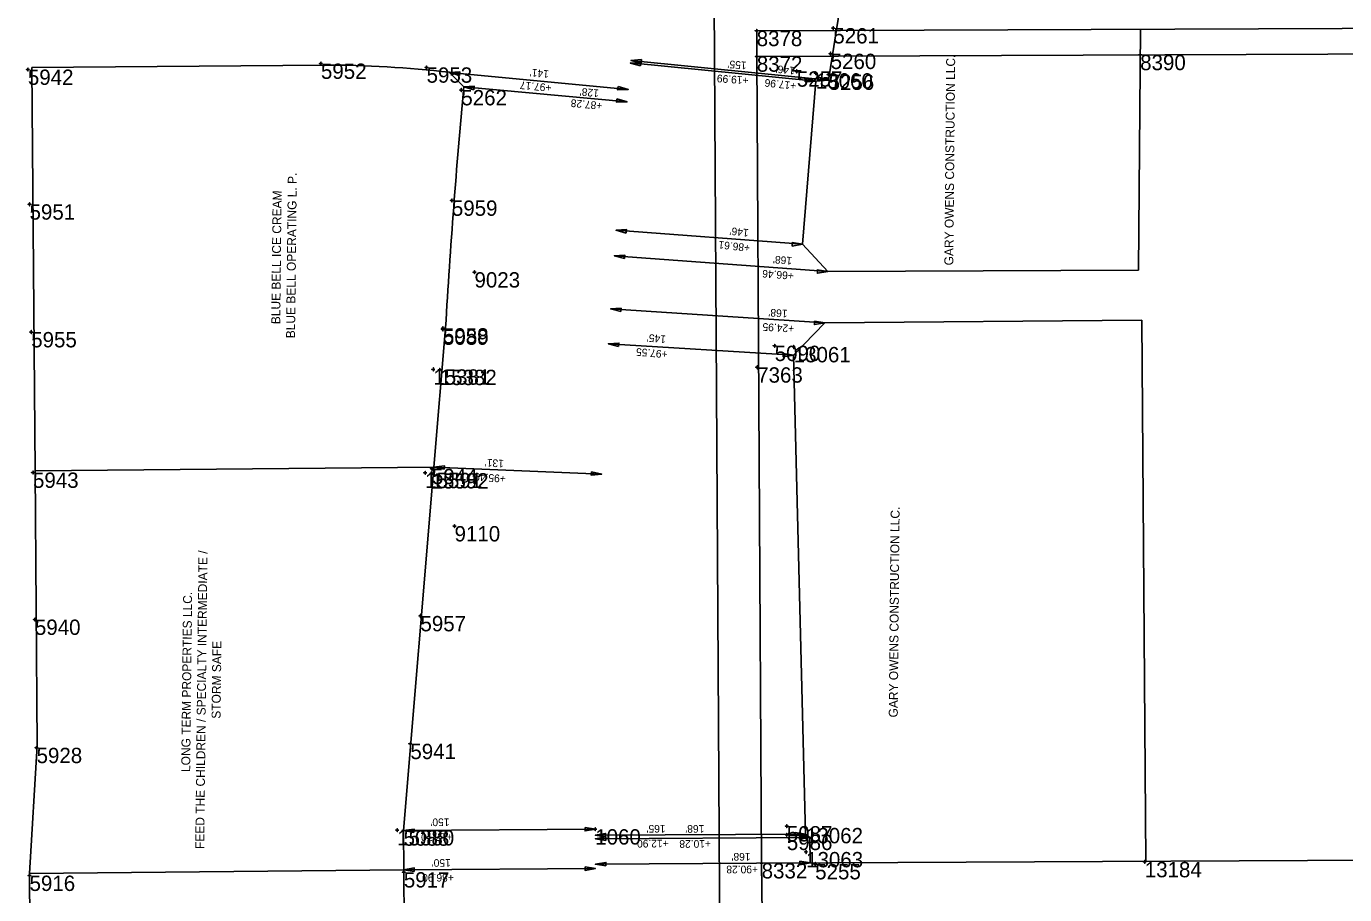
# Model space of a CAD drawing. Extents: x 2145146 to 2158053, y 137507 to 150829.
# Drawn here: x 2150359 to 2151391, y 146286 to 146965 of the extents above; entities that cross this region are included whole.
import ezdxf

# ---------------------------------------------------------------- set-up
doc = ezdxf.new("R2010")
doc.units = 0
for name, color, linetype in [('ALIGN_Cogo Points', 7, 'Continuous'), ('ALIGN_ROW Dimension', 7, 'Continuous'), ('ALIGN_ROW Line', 7, 'Continuous'), ('PLSS_Block Line', 7, 'Continuous'), ('PLSS_Property Line', 7, 'Continuous'), ('PLSS_Section Line', 7, 'Continuous'), ('PLSS_Text_TURNED OFF', 7, 'Continuous')]:
    doc.layers.add(name, color=color, linetype=linetype)

# ---------------------------------------------------------------- blocks, each defined once
blk = doc.blocks.new('Arrowhd')
at = {"layer": 'PLSS_Property Line'}
blk.add_lwpolyline([(0.125, -0.021), (0.125, 0.021), (0, 0)], close=True, dxfattribs=at)

msp = doc.modelspace()

# ---------------------------------------------------------------- linework, layer by layer
at = {"layer": 'ALIGN_Cogo Points'}
for points in [[(2150931, 146961.3), (2150931, 146962.5), (2150931, 146961.3), (2150929.8, 146961.3), (2150931, 146961.3), (2150931, 146960.1), (2150931, 146961.3), (2150932.2, 146961.3)], [(2150991, 146963.4), (2150991, 146964.6), (2150991, 146963.4), (2150989.8, 146963.4), (2150991, 146963.4), (2150991, 146962.2), (2150991, 146963.4), (2150992.2, 146963.4)], [(2150931.1, 146941.3), (2150931.1, 146942.5), (2150931.1, 146941.3), (2150929.9, 146941.3), (2150931.1, 146941.3), (2150931.1, 146940.1), (2150931.1, 146941.3), (2150932.3, 146941.3)], [(2150988.9, 146943.4), (2150988.9, 146944.6), (2150988.9, 146943.4), (2150987.7, 146943.4), (2150988.9, 146943.4), (2150988.9, 146942.2), (2150988.9, 146943.4), (2150990.1, 146943.4)], [(2151231.2, 146942.5), (2151231.2, 146943.7), (2151231.2, 146942.5), (2151230, 146942.5), (2151231.2, 146942.5), (2151231.2, 146941.3), (2151231.2, 146942.5), (2151232.4, 146942.5)], [(2150360.5, 146931), (2150360.5, 146932.2), (2150360.5, 146931), (2150359.3, 146931), (2150360.5, 146931), (2150360.5, 146929.8), (2150360.5, 146931), (2150361.7, 146931)], [(2150589.9, 146935.7), (2150589.9, 146936.9), (2150589.9, 146935.7), (2150588.7, 146935.7), (2150589.9, 146935.7), (2150589.9, 146934.5), (2150589.9, 146935.7), (2150591.1, 146935.7)], [(2150672.6, 146932.7), (2150672.6, 146933.9), (2150672.6, 146932.7), (2150671.4, 146932.7), (2150672.6, 146932.7), (2150672.6, 146931.5), (2150672.6, 146932.7), (2150673.8, 146932.7)], [(2150962.4, 146929.6), (2150962.4, 146930.8), (2150962.4, 146929.6), (2150961.2, 146929.6), (2150962.4, 146929.6), (2150962.4, 146928.4), (2150962.4, 146929.6), (2150963.6, 146929.6)], [(2150977.3, 146928.1), (2150977.3, 146929.3), (2150977.3, 146928.1), (2150976.1, 146928.1), (2150977.3, 146928.1), (2150977.3, 146926.9), (2150977.3, 146928.1), (2150978.5, 146928.1)], [(2150987.3, 146927.1), (2150987.3, 146928.3), (2150987.3, 146927.1), (2150986.1, 146927.1), (2150987.3, 146927.1), (2150987.3, 146925.9), (2150987.3, 146927.1), (2150988.5, 146927.1)], [(2150699.8, 146915), (2150699.8, 146916.2), (2150699.8, 146915), (2150698.6, 146915), (2150699.8, 146915), (2150699.8, 146913.8), (2150699.8, 146915), (2150701, 146915)], [(2150361.8, 146825.6), (2150361.8, 146826.8), (2150361.8, 146825.6), (2150360.6, 146825.6), (2150361.8, 146825.6), (2150361.8, 146824.4), (2150361.8, 146825.6), (2150363, 146825.6)], [(2150692.4, 146828.6), (2150692.4, 146829.8), (2150692.4, 146828.6), (2150691.2, 146828.6), (2150692.4, 146828.6), (2150692.4, 146827.4), (2150692.4, 146828.6), (2150693.6, 146828.6)], [(2150710.1, 146772.5), (2150710.1, 146773.7), (2150710.1, 146772.5), (2150708.9, 146772.5), (2150710.1, 146772.5), (2150710.1, 146771.3), (2150710.1, 146772.5), (2150711.3, 146772.5)], [(2150363.1, 146725.7), (2150363.1, 146726.9), (2150363.1, 146725.7), (2150361.9, 146725.7), (2150363.1, 146725.7), (2150363.1, 146724.5), (2150363.1, 146725.7), (2150364.3, 146725.7)], [(2150685.4, 146728.7), (2150685.4, 146729.9), (2150685.4, 146728.7), (2150684.2, 146728.7), (2150685.4, 146728.7), (2150685.4, 146727.5), (2150685.4, 146728.7), (2150686.6, 146728.7)], [(2150685.4, 146727.7), (2150685.4, 146728.9), (2150685.4, 146727.7), (2150684.2, 146727.7), (2150685.4, 146727.7), (2150685.4, 146726.5), (2150685.4, 146727.7), (2150686.6, 146727.7)], [(2150945.1, 146715), (2150945.1, 146716.2), (2150945.1, 146715), (2150943.9, 146715), (2150945.1, 146715), (2150945.1, 146713.8), (2150945.1, 146715), (2150946.3, 146715)], [(2150960, 146714), (2150960, 146715.2), (2150960, 146714), (2150958.8, 146714), (2150960, 146714), (2150960, 146712.8), (2150960, 146714), (2150961.2, 146714)], [(2150677.9, 146696.5), (2150677.9, 146697.7), (2150677.9, 146696.5), (2150676.7, 146696.5), (2150677.9, 146696.5), (2150677.9, 146695.3), (2150677.9, 146696.5), (2150679.1, 146696.5)], [(2150682.9, 146696.2), (2150682.9, 146697.4), (2150682.9, 146696.2), (2150681.7, 146696.2), (2150682.9, 146696.2), (2150682.9, 146695), (2150682.9, 146696.2), (2150684.1, 146696.2)], [(2150931.4, 146698.1), (2150931.4, 146699.3), (2150931.4, 146698.1), (2150930.2, 146698.1), (2150931.4, 146698.1), (2150931.4, 146696.9), (2150931.4, 146698.1), (2150932.6, 146698.1)], [(2150676.8, 146618.7), (2150676.8, 146619.9), (2150676.8, 146618.7), (2150675.6, 146618.7), (2150676.8, 146618.7), (2150676.8, 146617.5), (2150676.8, 146618.7), (2150678, 146618.7)], [(2150364.5, 146615.8), (2150364.5, 146617), (2150364.5, 146615.8), (2150363.3, 146615.8), (2150364.5, 146615.8), (2150364.5, 146614.6), (2150364.5, 146615.8), (2150365.7, 146615.8)], [(2150671.5, 146615.6), (2150671.5, 146616.8), (2150671.5, 146615.6), (2150670.3, 146615.6), (2150671.5, 146615.6), (2150671.5, 146614.4), (2150671.5, 146615.6), (2150672.7, 146615.6)], [(2150676.5, 146615.3), (2150676.5, 146616.5), (2150676.5, 146615.3), (2150675.3, 146615.3), (2150676.5, 146615.3), (2150676.5, 146614.1), (2150676.5, 146615.3), (2150677.7, 146615.3)], [(2150694.5, 146573.9), (2150694.5, 146575.1), (2150694.5, 146573.9), (2150693.3, 146573.9), (2150694.5, 146573.9), (2150694.5, 146572.7), (2150694.5, 146573.9), (2150695.7, 146573.9)], [(2150366, 146500.8), (2150366, 146502), (2150366, 146500.8), (2150364.8, 146500.8), (2150366, 146500.8), (2150366, 146499.6), (2150366, 146500.8), (2150367.2, 146500.8)], [(2150667.8, 146503.6), (2150667.8, 146504.8), (2150667.8, 146503.6), (2150666.6, 146503.6), (2150667.8, 146503.6), (2150667.8, 146502.4), (2150667.8, 146503.6), (2150669, 146503.6)], [(2150659.9, 146403.6), (2150659.9, 146404.8), (2150659.9, 146403.6), (2150658.7, 146403.6), (2150659.9, 146403.6), (2150659.9, 146402.4), (2150659.9, 146403.6), (2150661.1, 146403.6)], [(2150367.3, 146400.5), (2150367.3, 146401.7), (2150367.3, 146400.5), (2150366.1, 146400.5), (2150367.3, 146400.5), (2150367.3, 146399.3), (2150367.3, 146400.5), (2150368.5, 146400.5)], [(2150649.6, 146336.1), (2150649.6, 146337.3), (2150649.6, 146336.1), (2150648.4, 146336.1), (2150649.6, 146336.1), (2150649.6, 146334.9), (2150649.6, 146336.1), (2150650.8, 146336.1)], [(2150654.6, 146335.9), (2150654.6, 146337.1), (2150654.6, 146335.9), (2150653.4, 146335.9), (2150654.6, 146335.9), (2150654.6, 146334.7), (2150654.6, 146335.9), (2150655.8, 146335.9)], [(2150804.6, 146336.8), (2150804.6, 146338), (2150804.6, 146336.8), (2150803.4, 146336.8), (2150804.6, 146336.8), (2150804.6, 146335.6), (2150804.6, 146336.8), (2150805.8, 146336.8)], [(2150954.6, 146339.2), (2150954.6, 146340.4), (2150954.6, 146339.2), (2150953.4, 146339.2), (2150954.6, 146339.2), (2150954.6, 146338), (2150954.6, 146339.2), (2150955.8, 146339.2)], [(2150954.6, 146332.5), (2150954.6, 146333.7), (2150954.6, 146332.5), (2150953.4, 146332.5), (2150954.6, 146332.5), (2150954.6, 146331.3), (2150954.6, 146332.5), (2150955.8, 146332.5)], [(2150969.6, 146337.8), (2150969.6, 146339), (2150969.6, 146337.8), (2150968.4, 146337.8), (2150969.6, 146337.8), (2150969.6, 146336.6), (2150969.6, 146337.8), (2150970.8, 146337.8)], [(2150969.7, 146319), (2150969.7, 146320.2), (2150969.7, 146319), (2150968.5, 146319), (2150969.7, 146319), (2150969.7, 146317.8), (2150969.7, 146319), (2150970.9, 146319)], [(2150934.9, 146310.3), (2150934.9, 146311.5), (2150934.9, 146310.3), (2150933.7, 146310.3), (2150934.9, 146310.3), (2150934.9, 146309.1), (2150934.9, 146310.3), (2150936.1, 146310.3)], [(2150976.8, 146309.6), (2150976.8, 146310.8), (2150976.8, 146309.6), (2150975.6, 146309.6), (2150976.8, 146309.6), (2150976.8, 146308.4), (2150976.8, 146309.6), (2150978, 146309.6)], [(2151234.8, 146311.2), (2151234.8, 146312.4), (2151234.8, 146311.2), (2151233.6, 146311.2), (2151234.8, 146311.2), (2151234.8, 146310), (2151234.8, 146311.2), (2151236, 146311.2)], [(2150361.8, 146300.5), (2150361.8, 146301.7), (2150361.8, 146300.5), (2150360.6, 146300.5), (2150361.8, 146300.5), (2150361.8, 146299.3), (2150361.8, 146300.5), (2150363, 146300.5)], [(2150654.8, 146303.2), (2150654.8, 146304.4), (2150654.8, 146303.2), (2150653.6, 146303.2), (2150654.8, 146303.2), (2150654.8, 146302), (2150654.8, 146303.2), (2150656, 146303.2)]]:
    msp.add_lwpolyline(points, dxfattribs=at)
at = {"layer": 'ALIGN_ROW Dimension'}
for p, q in [((2150830.4, 146915.5), (2150690.5, 146928.8)), ((2150977.2, 146921.8), (2150832.4, 146936.2)), ((2150987.2, 146922.8), (2150832.6, 146938.2)), ((2150829.5, 146905.7), (2150701.7, 146917.6)), ((2150966.9, 146794.3), (2150821, 146805.3)), ((2150986.6, 146773.1), (2150819.5, 146785.3)), ((2150984.3, 146732.9), (2150816.6, 146743.8)), ((2150959.9, 146707.7), (2150814.9, 146716.5)), ((2150809.7, 146614.6), (2150678.4, 146620.1)), ((2150804.6, 146336.8), (2150654.6, 146335.9)), ((2150969.2, 146333), (2150804.6, 146332.1)), ((2150972.7, 146330.4), (2150804.7, 146329.4)), ((2150972.8, 146310.4), (2150804.8, 146309.4)), ((2150804.8, 146306), (2150654.8, 146305.1))]:
    msp.add_line(p, q, dxfattribs=at)
at = {"layer": 'ALIGN_ROW Line'}
for p, q in [((2150987.2, 146922.8), (2150996.4, 146980.2)), ((2150363.7, 146932.7), (2150592.8, 146934.5)), ((2150690.5, 146928.8), (2150701.7, 146917.6)), ((2150977.2, 146921.8), (2150966.9, 146794.3)), ((2150987.2, 146922.8), (2150977.2, 146921.8)), ((2150986.6, 146773.1), (2150966.9, 146794.3)), ((2150959.9, 146707.7), (2150984.3, 146732.9)), ((2150984.3, 146732.9), (2151232.4, 146734.9)), ((2150678.4, 146620.1), (2150687.5, 146729.1)), ((2150959.9, 146707.7), (2150969.2, 146333)), ((2150654.6, 146335.9), (2150678.4, 146620.1)), ((2150654.8, 146305.1), (2150654.6, 146335.9)), ((2150969.2, 146333), (2150972.7, 146330.4)), ((2150972.7, 146330.4), (2150972.8, 146310.4)), ((2150656.9, 145954.2), (2150654.8, 146305.1))]:
    msp.add_line(p, q, dxfattribs=at)
msp.add_lwpolyline([(2151230, 146774.1), (2150986.6, 146773.1)], dxfattribs=at)
for centre, radius, start, end in [((2150592.8, 146083), 851.5, 83.4143, 90), ((2156534.4, 146382.6), 5857.2, 174.75892, 176.60802)]:
    msp.add_arc(centre, radius, start, end, dxfattribs=at)
at = {"layer": 'PLSS_Block Line'}
for p, q in [((2150366.1, 146617.2), (2150363.7, 146932.7)), ((2150367.8, 146402.2), (2150366.1, 146617.2)), ((2150361.8, 146302.2), (2150367.8, 146402.2)), ((2150363.9, 145951.2), (2150361.8, 146302.2))]:
    msp.add_line(p, q, dxfattribs=at)
for points in [[(2150931, 146961.3), (2153549.3, 146971.8)], [(2150938.9, 145639.2), (2150935.2, 146270.3), (2150934.9, 146310.3), (2150931.1, 146941.3), (2150931, 146961.3)], [(2153549.4, 146951.8), (2150931.1, 146941.3)], [(2150934.9, 146310.3), (2153552, 146323)]]:
    msp.add_lwpolyline(points, dxfattribs=at)
at = {"layer": 'PLSS_Property Line'}
for p, q in [((2151232.4, 146734.9), (2151235.5, 146311.7)), ((2150366.1, 146617.2), (2150678.4, 146620.1)), ((2150654.8, 146305.1), (2150361.8, 146302.2))]:
    msp.add_line(p, q, dxfattribs=at)
msp.add_lwpolyline([(2151231.4, 146962.5), (2151230, 146774.1)], dxfattribs=at)
at = {"layer": 'PLSS_Section Line'}
msp.add_lwpolyline([(2150905.8, 145639), (2150890, 148284.8)], dxfattribs=at)

# ---------------------------------------------------------------- block references
at = {"layer": 'ALIGN_ROW Dimension'}
for p, xscale, yscale, rotation in [((2150832.6, 146938.2), 65, 65.00000000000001, -5.741718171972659), ((2150690.5, 146928.8), 65, 64.99999999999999, -7.374005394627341), ((2150832.2, 146936), 65, 65.00000000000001, -5.741718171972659), ((2150701.7, 146917.6), 65, 64.99999999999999, -7.374005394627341), ((2150977.2, 146921.8), 65, 65, 173.10657989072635), ((2150987.2, 146922.8), 64.99999999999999, 65, 174.47926723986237), ((2150830.4, 146915.5), 65, 64.99999999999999, 173.01404764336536), ((2150829.5, 146905.7), 65, 64.99999999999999, 172.79881966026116), ((2150821, 146805.3), 65, 65.00000000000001, -5.741718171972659), ((2150966.9, 146794.3), 65.00000000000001, 64.99999999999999, -179.65177652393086), ((2150819.5, 146785.3), 65, 65.00000000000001, -5.741718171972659), ((2150986.6, 146773.1), 65.00000000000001, 64.99999999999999, -179.65177652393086), ((2150816.6, 146743.8), 65, 65.00000000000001, -5.741718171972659), ((2150984.3, 146732.9), 65.00000000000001, 64.99999999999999, -179.65177652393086), ((2150814.9, 146716.5), 65, 65.00000000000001, -5.741718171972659), ((2150959.9, 146707.7), 65.00000000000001, 64.99999999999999, -179.65177652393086), ((2150678.4, 146620.1), 65, 65, -2.676263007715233), ((2150809.7, 146614.6), 65, 64.99999999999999, 176.73452931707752), ((2150654.6, 146335.9), 65, 65, -2.676263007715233), ((2150804.8, 146336.9), 65.00000000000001, 64.99999999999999, -179.65177652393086), ((2150804.6, 146332.1), 65, 65, 0.2668843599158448), ((2150804.7, 146329.4), 65, 65, 0.2668843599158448), ((2150969.2, 146333), 65.00000000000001, 64.99999999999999, -179.65177652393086), ((2150972.7, 146330.4), 65.00000000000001, 64.99999999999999, -179.65177652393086), ((2150804.8, 146309.4), 65, 65, 0.2668843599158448), ((2150972.8, 146310.4), 65.00000000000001, 64.99999999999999, -179.65177652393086), ((2150654.8, 146305.1), 65, 65, 0.2668843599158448), ((2150804.8, 146306), 65.00000000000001, 64.99999999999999, -179.65177652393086)]:
    msp.add_blockref('Arrowhd', p, dxfattribs=dict(at, xscale=xscale, yscale=yscale, rotation=rotation))

# ---------------------------------------------------------------- texts
at = {"layer": 'ALIGN_Cogo Points'}
for s, p in [('8378', (2150931, 146949.3)), ('5261', (2150991, 146951.4)), ('8372', (2150931.1, 146929.3)), ('5260', (2150988.9, 146931.4)), ('8390', (2151231.2, 146930.5)), ('5942', (2150360.5, 146919)), ('5952', (2150589.9, 146923.7)), ('5953', (2150672.6, 146920.7)), ('5257', (2150962.4, 146917.6)), ('13060', (2150977.3, 146916.1)), ('5256', (2150987.3, 146915.1)), ('5262', (2150699.8, 146903)), ('5951', (2150361.8, 146813.6)), ('5959', (2150692.4, 146816.6)), ('9023', (2150710.1, 146760.5)), ('5955', (2150363.1, 146713.7)), ('5089', (2150685.4, 146715.7)), ('5958', (2150685.4, 146716.7)), ('5090', (2150945.1, 146703)), ('13061', (2150960, 146702)), ('15381', (2150677.9, 146684.5)), ('15382', (2150682.9, 146684.2)), ('7363', (2150931.4, 146686.1)), ('5943', (2150364.5, 146603.8)), ('15591', (2150671.5, 146603.6)), ('5944', (2150676.8, 146606.7)), ('15592', (2150676.5, 146603.3)), ('9110', (2150694.5, 146561.9)), ('5940', (2150366, 146488.8)), ('5957', (2150667.8, 146491.6)), ('5941', (2150659.9, 146391.6)), ('5928', (2150367.3, 146388.5)), ('15380', (2150649.6, 146324.1)), ('5088', (2150654.6, 146323.9)), ('1060', (2150804.6, 146324.8)), ('5087', (2150954.6, 146327.2)), ('5986', (2150954.6, 146320.5)), ('13062', (2150969.6, 146325.8)), ('8332', (2150934.9, 146298.3)), ('13063', (2150969.7, 146307)), ('5255', (2150976.8, 146297.6)), ('13184', (2151234.8, 146299.2)), ('5916', (2150361.8, 146288.5)), ('5917', (2150654.8, 146291.2))]:
    msp.add_text(s, height=12, dxfattribs=at).set_placement(p)
at = {"layer": 'ALIGN_ROW Dimension'}
for s, rotation, p in [("141'", 174.6652, (2150768.6, 146930.3)), ("155'", 175.7952, (2150923.3, 146937.1)), ("146'", 174.0109, (2150961.1, 146932.9)), ('+97.17', 174.6652, (2150770.6, 146919.5)), ('+19.99', 175.7952, (2150924.8, 146925.3)), ('+17.96', 174.0109, (2150962.2, 146921.1)), ("128'", 174.6652, (2150807.7, 146915.3)), ('+87.28', 174.6652, (2150810.4, 146905.5)), ("146'", 173.7185, (2150925, 146806.1)), ('+86.61', 173.7185, (2150926.1, 146794.3)), ("168'", 175.5833, (2150958.9, 146784.3)), ('+66.46', 175.5833, (2150960.3, 146772.5)), ("168'", 176.3947, (2150955.3, 146743)), ('+24.95', 176.3947, (2150960.5, 146731.2)), ("145'", 175.0992, (2150860.2, 146722.9)), ('+97.55', 175.0992, (2150861.5, 146711.1)), ("131'", 176.11, (2150733.3, 146625.6)), ('+95.49', 176.11, (2150734.8, 146613.8)), ("150'", 180.3718, (2150690.5, 146345.3)), ('+17.70', 180.3718, (2150693, 146333.7)), ("165'", 180.3718, (2150859.7, 146340.2)), ("168'", 180.3718, (2150890, 146340.1)), ('+12.90', 180.3718, (2150862.1, 146328.6)), ('+10.28', 180.3718, (2150895.2, 146328.4)), ("150'", 180.3718, (2150691.5, 146313.5)), ("168'", 180.3718, (2150926.2, 146318.3)), ('+86.90', 180.3718, (2150693.9, 146301.9)), ('+90.28', 180.3718, (2150932, 146308.4))]:
    msp.add_text(s, height=6, rotation=rotation, dxfattribs=at).set_placement(p)
at = {"layer": 'PLSS_Text_TURNED OFF'}
for s, rotation, p in [('GARY OWENS CONSTRUCTION LLC.', 89.4808, (2151084.9, 146777.8)), ('BLUE BELL OPERATING L. P.', 89.3643, (2150569.6, 146720.8)), ('BLUE BELL ICE CREAM', 89.3643, (2150558, 146731.8)), ('GARY OWENS CONSTRUCTION LLC.', 89.4808, (2151041.4, 146424.2)), ('FEED THE CHILDREN / SPECIALTY INTERMEDIATE /', 89.3643, (2150498.5, 146321.3)), ('LONG TERM PROPERTIES LLC.', 89.3643, (2150487.5, 146381.5)), ('STORM SAFE', 89.3643, (2150511.3, 146423.2))]:
    msp.add_text(s, height=7, rotation=rotation, dxfattribs=at).set_placement(p)

doc.saveas('drawing.dxf')
